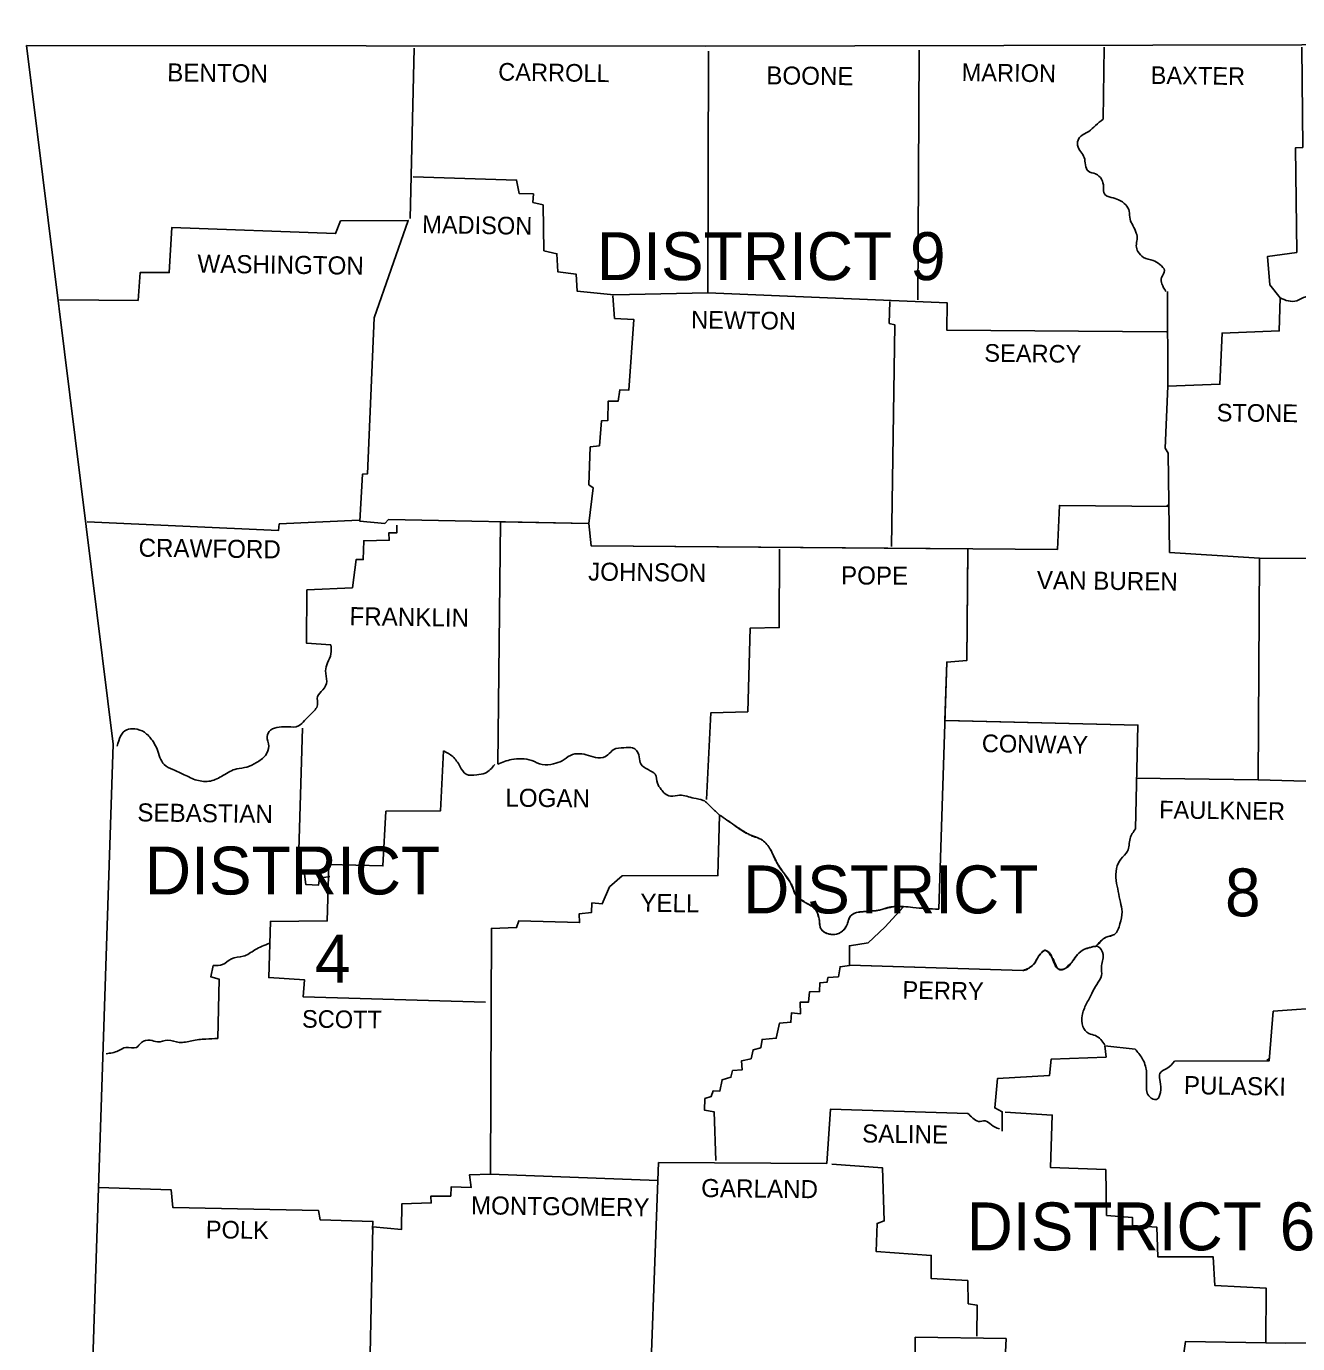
# Model space of a CAD drawing. Extents: x -17668 to 16999, y -17303 to 5867.
# Drawn here: x -17668 to -16002, y -8859 to -7133 of the extents above; entities that cross this region are included whole.
import ezdxf

# ---------------------------------------------------------------- set-up
doc = ezdxf.new("R2010")
doc.units = 0
for name, color, linetype in [('1', 7, 'Continuous'), ('2', 7, 'Continuous'), ('3', 7, 'Continuous'), ('45', 7, 'Continuous')]:
    doc.layers.add(name, color=color, linetype=linetype)

msp = doc.modelspace()

# ---------------------------------------------------------------- linework, layer by layer
at = {"layer": '1'}
for points in [[(-17667.8, -7158.5), (-16777.9, -7159.1), (-15996.9, -7157.4), (-15075.6, -7143.1), (-14648.6, -7133.2)], [(-17667.8, -7158.5), (-17553.9, -8073.2), (-17603.4, -9566.3)], [(-17159.8, -7161.9), (-17164.8, -7384.7)], [(-17160.9, -7330.3), (-17025.5, -7334.7), (-17022.2, -7352.3), (-17003.5, -7352.8), (-17004.1, -7363.8), (-16990.9, -7367.1), (-16989.8, -7427.1), (-16972.7, -7431), (-16971.6, -7454.6), (-16947.4, -7457.9), (-16946.3, -7480), (-16898.4, -7484.9), (-16775.1, -7482.2), (-16774, -7165.7)], [(-16498.3, -7164.6), (-16500, -7491.5)], [(-16256.1, -7160.7), (-16257.2, -7254.9)], [(-15996.9, -7160.7), (-15995.8, -7291.7), (-16005.2, -7292.3), (-16003.5, -7429.3), (-16042.1, -7434.8), (-16038.8, -7471.7), (-16025.5, -7488.8), (-16026.6, -7532.2), (-16101.5, -7535), (-16104.2, -7602.1), (-16172.5, -7604.3), (-16175.8, -7685.8), (-16171.9, -7692.4), (-16170.3, -7822.3), (-16052.5, -7830), (-16054.2, -8120), (-15960.6, -8122.8), (-15960.6, -8417.8), (-16034.4, -8423.3), (-16039.9, -8488.2), (-16163.7, -8488.8)], [(-17624.3, -7491.5), (-17521.4, -7492.1), (-17518.7, -7455.7), (-17480.7, -7455.7), (-17477.4, -7396.9), (-17262.7, -7404.6), (-17256.1, -7388), (-17167.5, -7387.5), (-17212.1, -7515.2), (-17220.9, -7719.4), (-17227.5, -7719.9), (-17230.8, -7781.5), (-17198.4, -7784.3), (-17193.4, -7779.3), (-16930.9, -7784.3), (-16928.1, -7813.5)], [(-16899.5, -7486), (-16897.3, -7515.7), (-16872, -7517.4), (-16878.6, -7609.8), (-16890.2, -7609.3), (-16892.4, -7624.1), (-16905.6, -7624.1), (-16906.1, -7649.5), (-16914.4, -7650), (-16917.1, -7682.5), (-16929.2, -7684.1), (-16930.9, -7733.7), (-16925.4, -7737.5), (-16930.9, -7784.3)], [(-16775.1, -7482.2), (-16461.4, -7495.4), (-16462, -7531.1), (-16174.1, -7533.3)], [(-16172.5, -7604.3), (-16173, -7480.5)], [(-16536.8, -7493.7), (-16537.4, -7522.3), (-16530.2, -7524), (-16534.6, -7814.6)], [(-16928.1, -7813.5), (-16317.2, -7818.4), (-16314.5, -7760.6), (-16172.5, -7762.3)], [(-16174.1, -7761.7), (-16172.5, -7760.1)], [(-17588, -7782.1), (-17337.6, -7793.7), (-17336.5, -7784.9), (-17231.9, -7779.9)], [(-17182.4, -7786.5), (-17182.4, -7796.4), (-17192.8, -7796.4), (-17192.3, -7806.3), (-17225.9, -7806.9), (-17226.4, -7831.6), (-17235.8, -7831.6), (-17240.7, -7868.5), (-17300.2, -7871.3), (-17300.7, -7941.2), (-17268.8, -7943.4)], [(-17046.5, -7782.1), (-17050.3, -8099.7)], [(-16681, -7817.9), (-16681.6, -7920.8), (-16719.5, -7921.3), (-16722.8, -8030.9), (-16771.3, -8032.5), (-16776.8, -8145.9)], [(-16434.5, -7820.6), (-16435.6, -7963.7), (-16462, -7965.9), (-16472.4, -8289.5)], [(-16052.5, -7830), (-15769.6, -7831.6), (-15745.4, -7820.1), (-15747.1, -8035.3), (-15763.6, -8042.4), (-15778.4, -8055.1), (-15783.4, -8060), (-15783.9, -8121.7), (-15963.9, -8121.7)], [(-17306.2, -8052.3), (-17311.7, -8241.6), (-17303.5, -8243.8), (-17301.8, -8257.1), (-17285.3, -8258.2), (-17283.7, -8248.8), (-17270.4, -8246.6)], [(-16463.1, -8042.4), (-16211.6, -8048.5), (-16214.9, -8184.4)], [(-17121.3, -8082), (-17125.2, -8160.7), (-17196.7, -8161.3), (-17200.6, -8232.8), (-17271.5, -8231.2), (-17273.7, -8304.9), (-17348, -8305.5), (-17350.2, -8379.2), (-17303.5, -8382), (-17305.1, -8404.5), (-17066.3, -8411.2)], [(-16214.3, -8117.8), (-16054.2, -8120)], [(-16759.7, -8166.2), (-16761.9, -8245.5), (-16887.4, -8246), (-16903.9, -8260.4), (-16913.3, -8282.4), (-16927, -8281.3), (-16927.6, -8293.9), (-16943.5, -8295.6), (-16943, -8307.1), (-17022.8, -8304.9), (-17025.5, -8313.7), (-17058.6, -8314.8), (-17059.7, -8636.8), (-17087.2, -8637.3), (-17085, -8653.9), (-17111.4, -8653.3), (-17111.9, -8665.4), (-17137.8, -8665.4), (-17137.3, -8674.2), (-17175.8, -8675.3), (-17176.3, -8708.9), (-17213.8, -8705.6), (-17219.8, -8976.4)], [(-16523.6, -8291.7), (-16543.4, -8313.2), (-16564.9, -8333.6), (-16589.7, -8337.4), (-16589.7, -8363.3), (-16601.8, -8364.9), (-16604, -8378.1), (-16617.7, -8379.2), (-16618.8, -8385.3), (-16628.2, -8385.8), (-16628.7, -8397.4), (-16641.9, -8397.9), (-16643, -8411.2), (-16654.1, -8411.2), (-16653.5, -8426.6), (-16665.6, -8425.5), (-16666.2, -8437.6), (-16681, -8438.7), (-16685.4, -8458.5), (-16704.1, -8460.1), (-16705.8, -8471.1), (-16715.7, -8473.9), (-16718.4, -8485.5), (-16731.1, -8488.2), (-16730, -8499.8), (-16742.7, -8500.9), (-16744.9, -8509.7), (-16756.4, -8513), (-16759.2, -8527.8), (-16768, -8527.3), (-16770.7, -8535), (-16779, -8537.7), (-16779.5, -8552.6), (-16766.9, -8554.8), (-16764.7, -8618.6)], [(-17416.8, -8459), (-17415.2, -8381.4), (-17426.2, -8378.1), (-17422.9, -8363.3)], [(-16362.4, -8369.9), (-16589.1, -8362.7)], [(-16215.4, -8472.8), (-16255, -8468.4), (-16253.4, -8483.2), (-16325.5, -8486), (-16327.7, -8507.5), (-16395.4, -8511.3), (-16399.2, -8549.8), (-16389.3, -8554.8), (-16389.3, -8580.1)], [(-16042.6, -8487.7), (-16039.9, -8484.9)], [(-16434.5, -8557), (-16614.4, -8551.5), (-16619.4, -8622.5), (-16839.5, -8621.4), (-16840.6, -8645.1)], [(-16385.5, -8555.3), (-16323.8, -8559.2), (-16326, -8628), (-16253.9, -8630.7), (-16252.8, -8690.7), (-16218.7, -8693.5), (-16218.7, -8703.9), (-16186.8, -8706.1), (-16185.7, -8744.7), (-16113.1, -8744.7), (-16110.9, -8782.6), (-16043.7, -8785.9), (-16044.3, -8857.5)], [(-16612.8, -8623.6), (-16546.2, -8628.5), (-16544, -8697.9), (-16553.3, -8701.2), (-16554.4, -8738.1), (-16482.3, -8743), (-16482.3, -8773.3), (-16434.5, -8776), (-16433.9, -8806.3), (-16422.4, -8808), (-16422.9, -8848.7)], [(-16840.6, -8645.1), (-17059.7, -8636.8)], [(-17573.1, -8653.9), (-17477.9, -8657.2), (-17475.7, -8680.3), (-17285.3, -8684.1), (-17283.1, -8696.2), (-17213.8, -8698.4), (-17214.3, -8708.9)], [(-16840.6, -8645.1), (-16853.3, -8987.9)], [(-15387.7, -8794.2), (-15595.7, -8788.7), (-15596.8, -8856.4), (-16017.8, -8858)], [(-16849.4, -8942.2), (-16534.6, -8946.6), (-16528.6, -8894.4), (-16503.8, -8894.4), (-16503.3, -8850.3), (-16384.4, -8852), (-16385.5, -8878.4), (-16354.7, -8880.6), (-16354.7, -8929), (-16334.8, -8930.7)], [(-16334.8, -8930.7), (-16304, -8926.3), (-16301.8, -8907.6), (-16283.7, -8904.3), (-16282.6, -8893.3), (-16154.3, -8889.4), (-16149.4, -8855.8), (-16017.8, -8858)]]:
    msp.add_lwpolyline(points, dxfattribs=at)
for points in [[(-16257.2, -7254.9), (-16267.2, -7263.1), (-16276, -7270.8), (-16289.2, -7280.2), (-16290.8, -7289), (-16286.4, -7297.8), (-16282, -7304.9), (-16280.4, -7314.8), (-16276.5, -7323.1), (-16267.2, -7326.4), (-16259.4, -7333.6), (-16256.7, -7343.5), (-16255.6, -7352.8), (-16246.8, -7357.2), (-16236.9, -7360.5), (-16227.5, -7367.1), (-16223.1, -7375.4), (-16222, -7385.8), (-16218.2, -7394.1), (-16213.8, -7404), (-16212.7, -7412.3), (-16213.8, -7420.5), (-16211.6, -7428.2), (-16204.4, -7435.9), (-16191.8, -7439.8), (-16182.9, -7445.3), (-16176.9, -7453), (-16180.7, -7462.3), (-16180.2, -7470.6), (-16175.2, -7480.5)], [(-16025.5, -7488.8), (-16003.5, -7492.6), (-15990.3, -7487.7), (-15981, -7502), (-15976, -7513), (-15967.8, -7528.9), (-15954.6, -7533.9), (-15944.6, -7542.7), (-15944.6, -7552.1), (-15953.4, -7560.9), (-15960.1, -7569.7), (-15957.9, -7580.1), (-15955.7, -7594.4), (-15955.7, -7608.2), (-15959, -7620.8), (-15961.7, -7632.4), (-15959, -7642.3), (-15948.5, -7640.7), (-15937.5, -7632.4), (-15925.9, -7632.4), (-15914.9, -7638.5), (-15903.4, -7648.9), (-15891.8, -7646.7), (-15882.5, -7644), (-15869.2, -7640.1), (-15859.9, -7645.1), (-15851.6, -7651.7), (-15841.7, -7662.1), (-15832.4, -7668.7), (-15820.3, -7674.8), (-15805.4, -7678.6), (-15791.6, -7688), (-15789.4, -7703.9), (-15790, -7717.7), (-15791.1, -7734.8), (-15792.2, -7753.5), (-15790.5, -7771.6), (-15784.5, -7783.8), (-15776.8, -7798.1), (-15774.6, -7811.3), (-15775.1, -7832.2)], [(-17268.8, -7943.4), (-17268.8, -7954.9), (-17273.2, -7967), (-17275.9, -7977.5), (-17274.3, -7991.2), (-17279.3, -8002.2), (-17286.4, -8011), (-17286.4, -8022.1), (-17294.7, -8033.6), (-17303.5, -8042.4), (-17311.2, -8049.6), (-17324.9, -8050.7), (-17336.5, -8051.2), (-17348, -8055.1), (-17352.4, -8063.3), (-17350.2, -8076), (-17354.7, -8088.1), (-17366.2, -8097.5), (-17378.9, -8103.5), (-17392.1, -8105.7), (-17410.2, -8114.5), (-17426.7, -8121.7), (-17444.4, -8120.6), (-17460.9, -8113.4), (-17475.7, -8106.8), (-17487.3, -8100.2), (-17496.6, -8079.8), (-17502.7, -8068.8), (-17513.2, -8057.8), (-17525.8, -8053.4), (-17536.3, -8054.5), (-17548.9, -8076)], [(-17121.3, -8082), (-17109.2, -8089.7), (-17099.8, -8102.4), (-17091.6, -8112.9), (-17077.8, -8113.4), (-17066.8, -8111.2), (-17054.2, -8100.2)], [(-17050.3, -8099.7), (-17032.1, -8093.6), (-17018.9, -8092.5), (-17005.7, -8094.7), (-16992, -8100.2), (-16977.1, -8099.1), (-16966.1, -8095.3), (-16955.1, -8088.1), (-16943, -8085.9), (-16931.4, -8088.1), (-16919.3, -8091.4), (-16906.1, -8087.5), (-16898.4, -8080.4), (-16885.2, -8078.2), (-16873.6, -8078.2), (-16865.4, -8087.5), (-16863.7, -8097.5), (-16853.3, -8106.8), (-16843.9, -8112.9), (-16841.2, -8124.4), (-16836.2, -8132.7), (-16831.3, -8138.2), (-16824.1, -8141.5), (-16812, -8140.4), (-16793.3, -8144.2), (-16781.2, -8147), (-16770.2, -8156.3), (-16759.7, -8166.2)], [(-16759.7, -8166.2), (-16740.5, -8179.5), (-16722.3, -8191), (-16703.6, -8199.3), (-16693.1, -8211.4), (-16683.8, -8230.1), (-16676.1, -8241.6), (-16666.2, -8256), (-16659, -8271.9), (-16647.4, -8280.7), (-16635.3, -8288.4), (-16629.3, -8302.2), (-16626.5, -8315.9), (-16613.3, -8322.5), (-16600.7, -8319.8), (-16593.5, -8311.5), (-16586.9, -8297.2), (-16572, -8292.8), (-16552.8, -8291.2), (-16530.8, -8286.2), (-16506.6, -8287.3), (-16472.4, -8289.5)], [(-16214.9, -8184.4), (-16222, -8197.1), (-16225.3, -8213.6), (-16234.1, -8224), (-16239.6, -8236.1), (-16240.2, -8252.1), (-16237.4, -8266.4), (-16234.7, -8280.2), (-16232.5, -8292.8), (-16235.2, -8308.8), (-16242.4, -8322.5), (-16253.4, -8326.4), (-16263.8, -8335.8)], [(-17422.9, -8363.3), (-17410.8, -8362.2), (-17399.2, -8354.5), (-17383.8, -8351.2), (-17368.4, -8342.9), (-17349.1, -8334.1)], [(-16362.4, -8369.9), (-16348.6, -8362.2), (-16341.4, -8350.6), (-16332.6, -8343.5), (-16323.8, -8353.4), (-16316.1, -8367.7), (-16307.9, -8367.7), (-16297.4, -8357.8), (-16290.8, -8349), (-16282.6, -8342.4), (-16273.8, -8339.6), (-16264.4, -8338.5), (-16257.2, -8349), (-16259.4, -8365.5), (-16259.4, -8376.5), (-16265.5, -8388), (-16272.1, -8400.1), (-16279.3, -8413.9), (-16284.8, -8428.8), (-16283.7, -8443.1), (-16276, -8452.4), (-16267.2, -8455.2), (-16255, -8467.3)], [(-17416.8, -8459), (-17432.8, -8459.6), (-17451, -8461.8), (-17467.5, -8464), (-17482.3, -8461.2), (-17496.1, -8463.4), (-17505.4, -8461.2), (-17517, -8464), (-17523.6, -8470.6), (-17537.4, -8470.6), (-17547.3, -8475), (-17563.2, -8478.8)], [(-16215.4, -8472.8), (-16206.1, -8484.9), (-16200.6, -8501.4), (-16200.6, -8520.1), (-16196.2, -8535.5), (-16187.4, -8538.8), (-16181.8, -8525.6), (-16182.9, -8512.4), (-16182.9, -8504.7), (-16173.6, -8498.1), (-16163.7, -8488.8)], [(-16393.2, -8577.4), (-16403.6, -8571.9), (-16411.9, -8566.9), (-16420.7, -8567.5), (-16427.9, -8563.1), (-16434.5, -8557)]]:
    msp.add_spline(points, degree=3, dxfattribs=at)
at = {"layer": '45'}
msp.add_line((-17046.5, -7782.1), (-17050.3, -8099.7), dxfattribs=at)
for points in [[(-16214.9, -8184.4), (-16211.6, -8048.5), (-16464.4, -8042.4), (-16462, -7965.9), (-16435.6, -7963.7), (-16434.4, -7817.5), (-16928.1, -7813.5), (-16930.9, -7784.3), (-17046.5, -7782.1)], [(-16518.9, -8286.6), (-16543.4, -8313.2), (-16564.9, -8333.6), (-16589.7, -8337.4), (-16589.7, -8362.7), (-16362.4, -8369.9)]]:
    msp.add_lwpolyline(points, dxfattribs=at)
for points in [[(-17050.3, -8099.7), (-17032.1, -8093.6), (-17018.9, -8092.5), (-17005.7, -8094.7), (-16992, -8100.2), (-16977.1, -8099.1), (-16966.1, -8095.3), (-16955.1, -8088.1), (-16943, -8085.9), (-16931.4, -8088.1), (-16919.3, -8091.4), (-16906.1, -8087.5), (-16898.4, -8080.4), (-16885.2, -8078.2), (-16873.6, -8078.2), (-16865.4, -8087.5), (-16863.7, -8097.5), (-16853.3, -8106.8), (-16843.9, -8112.9), (-16841.2, -8124.4), (-16836.2, -8132.7), (-16831.3, -8138.2), (-16824.1, -8141.5), (-16812, -8140.4), (-16793.3, -8144.2), (-16781.2, -8147), (-16770.2, -8156.3), (-16759.7, -8166.2)], [(-16759.7, -8166.2), (-16740.5, -8179.5), (-16731.5, -8185.4), (-16726.9, -8188.2), (-16722.3, -8191), (-16717.7, -8193.3), (-16712.9, -8195), (-16708.1, -8196.8), (-16705.8, -8197.9), (-16703.6, -8199.3), (-16697.7, -8204.7), (-16693.1, -8211.4), (-16690.7, -8216), (-16688.6, -8220.8), (-16686.3, -8225.6), (-16683.8, -8230.1), (-16678.7, -8237.7)], [(-16266.8, -8338.4), (-16253.4, -8326.4), (-16242.4, -8322.5), (-16235.2, -8308.8), (-16232.5, -8292.8), (-16234.7, -8280.2), (-16237.4, -8266.4), (-16240.2, -8252.1), (-16239.6, -8236.1), (-16234.1, -8224), (-16225.3, -8213.6), (-16222, -8197.1), (-16214.9, -8184.4)], [(-16678.7, -8237.7), (-16676.1, -8241.6), (-16666.2, -8256), (-16664.2, -8259.9), (-16662.9, -8264.1), (-16661.4, -8268.3), (-16660.4, -8270.2), (-16659, -8271.9), (-16653.4, -8276.6), (-16647.4, -8280.7), (-16646, -8281.7), (-16644.4, -8282.6), (-16641.3, -8284.3), (-16636.7, -8287.2), (-16636, -8287.8), (-16635.3, -8288.4), (-16633, -8291.5), (-16631.5, -8294.9), (-16630.4, -8298.6), (-16629.3, -8302.2), (-16628.9, -8303.9), (-16628.7, -8305.6), (-16628.6, -8309.1), (-16628.1, -8312.6), (-16627.5, -8314.3), (-16627.1, -8315.1), (-16626.5, -8315.9), (-16623.7, -8318.8), (-16620.4, -8320.7), (-16616.9, -8321.9), (-16615.1, -8322.3)], [(-16615.1, -8322.3), (-16613.3, -8322.5), (-16610.2, -8322.7), (-16606.9, -8322.4), (-16603.7, -8321.5), (-16600.7, -8319.8), (-16598.5, -8317.9), (-16596.6, -8315.9), (-16593.5, -8311.5), (-16592.6, -8309.8), (-16591.9, -8307.9), (-16590.8, -8304), (-16589.5, -8300.3), (-16588.4, -8298.6), (-16587.7, -8297.9), (-16586.9, -8297.2), (-16579.7, -8294), (-16572, -8292.8), (-16567.2, -8292.4), (-16562.4, -8292.1), (-16557.6, -8291.7), (-16552.8, -8291.2), (-16547.3, -8289.9), (-16541.8, -8288.3), (-16536.3, -8286.8), (-16530.8, -8286.2), (-16518.9, -8286.6)], [(-16362.4, -8369.9), (-16361.5, -8369.8), (-16360.6, -8369.6), (-16358.8, -8369.1), (-16355.3, -8367.4), (-16351.9, -8365), (-16350.2, -8363.7), (-16348.6, -8362.2), (-16347.4, -8360.8), (-16346.4, -8359.4), (-16344.9, -8356.4), (-16343.4, -8353.5), (-16341.4, -8350.6), (-16340.4, -8349.4), (-16339.3, -8348.1), (-16337, -8345.6), (-16336, -8344.6), (-16335.4, -8344.2), (-16334.8, -8343.8), (-16333.7, -8343.4), (-16333.2, -8343.4), (-16332.9, -8343.4), (-16332.6, -8343.5), (-16331.4, -8344.1), (-16330.3, -8344.9), (-16329.7, -8345.5), (-16329.2, -8346.1), (-16328.1, -8347.4), (-16325.9, -8350.4), (-16324.9, -8351.9), (-16323.8, -8353.4), (-16323.2, -8354.2), (-16321.7, -8356.9), (-16320.1, -8360.7), (-16318.8, -8363.5)], [(-16318.8, -8363.5), (-16318.4, -8364.4), (-16317.4, -8366.1), (-16316.8, -8366.9), (-16316.1, -8367.7), (-16315.3, -8368.3), (-16314.8, -8368.6), (-16314.3, -8368.8), (-16312.1, -8369.1), (-16309.8, -8368.7), (-16307.9, -8367.7), (-16305.1, -8365.4), (-16302.4, -8363), (-16299.8, -8360.5), (-16297.4, -8357.8), (-16295.7, -8355.6), (-16294.2, -8353.3), (-16292.6, -8351.1), (-16290.8, -8349), (-16287, -8345.3), (-16284.9, -8343.7), (-16282.6, -8342.4), (-16280.4, -8341.4), (-16278.2, -8340.7), (-16276, -8340.2), (-16273.8, -8339.6), (-16271.4, -8338.9), (-16269.1, -8338.3), (-16266.8, -8338.4)]]:
    msp.add_spline(points, degree=3, dxfattribs=at)

# ---------------------------------------------------------------- texts
at = {"layer": '2'}
for s, height, rotation, p in [('BENTON', 23.67, 359.2527, (-17483.4, -7205.3)), ('CARROLL', 23.11, 359.1481, (-17049.8, -7204.2)), ('BOONE', 23.67, 359.4001, (-16698.6, -7209.2)), ('MARION', 23.11, 359.1854, (-16442.7, -7204.8)), ('BAXTER', 23.11, 359.2559, (-16195.1, -7208.6)), ('MADISON', 23.11, 359.0906, (-17149.4, -7404)), ('WASHINGTON', 23.66, 359.232, (-17443.8, -7455.7)), ('NEWTON', 23.11, 359.2717, (-16797.1, -7528.9)), ('SEARCY', 23.11, 359.2527, (-16413, -7572.4)), ('STONE', 23.11, 359.4001, (-16108.6, -7650.6)), ('CRAWFORD', 23.66, 359.2771, (-17520.9, -7827.8)), ('JOHNSON', 23.67, 359.3514, (-16932, -7859.1)), ('POPE', 23.67, 359.6155, (-16600.7, -7864.1)), ('VAN BUREN', 23.67, 359.3508, (-16344.2, -7870.2)), ('FRANKLIN', 23.67, 359.1815, (-17244.6, -7917.5)), ('CONWAY', 23.11, 359.0371, (-16416.3, -8083.7)), ('LOGAN', 23.67, 359.3969, (-17040.4, -8155.2)), ('SEBASTIAN', 23.66, 359.2816, (-17522.5, -8174.5)), ('FAULKNER', 23.11, 359.2486, (-16184, -8170.6)), ('YELL', 23.67, 359.1987, (-16863.7, -8292.8)), ('PERRY', 23.11, 359.0858, (-16520.3, -8406.8)), ('SCOTT', 23.11, 359.4063, (-17306.8, -8444.7)), ('PULASKI', 23.67, 359.053, (-16151.6, -8531.7)), ('SALINE', 23.67, 359.1491, (-16573.1, -8595)), ('GARLAND', 23.67, 359.3658, (-16783.9, -8666.5)), ('MONTGOMERY', 23.67, 359.2944, (-17085.5, -8689.1)), ('POLK', 23.11, 359.2152, (-17432.8, -8720.5))]:
    msp.add_text(s, height=height, rotation=rotation, dxfattribs=at).set_placement(p)
at = {"layer": '3'}
for s, height, p in [('DISTRICT 9', 62.74, (-16920.4, -7465.6)), ('DISTRICT', 62.74, (-17512.6, -8270.3)), ('DISTRICT', 62.74, (-16728.9, -8295)), ('8', 62.7, (-16097.6, -8298.9)), ('4', 62.7, (-17289.7, -8385.8)), ('DISTRICT 6', 62.74, (-16436.1, -8736.4))]:
    msp.add_text(s, height=height, dxfattribs=at).set_placement(p)

doc.saveas('drawing.dxf')
